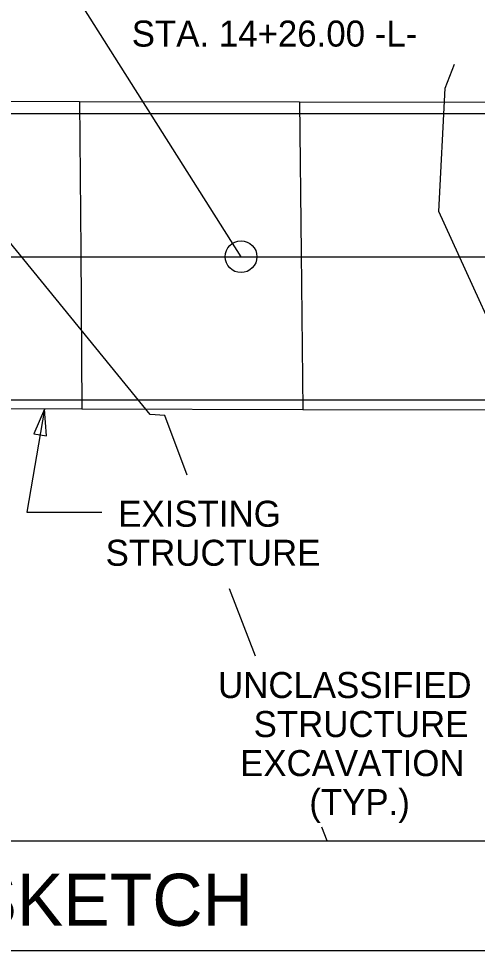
# Model space of a CAD drawing. Extents: x -20 to 509, y -659 to 21.
# Drawn here: x 118.1 to 153.4, y -423.4 to -351.8 of the extents above; entities that cross this region are included whole.
import ezdxf

# ---------------------------------------------------------------- set-up
doc = ezdxf.new("R2010")
doc.units = 0
for name, color, linetype in [('Arrowhead Terminators CELL', 7, 'Continuous'), ('Dimension Lines', 7, 'Continuous'), ('Exist Hydro Stream or Body of Water', 7, 'Continuous'), ('Exist Structure Major Deck Tunnel Box Culvert', 7, 'Continuous'), ('Plan Sheet CELL', 7, 'Continuous'), ('Prop EOT', 7, 'Continuous'), ('Prop Horizontal Alignment', 7, 'Continuous'), ('Text', 7, 'Continuous'), ('Title Text', 7, 'Continuous')]:
    doc.layers.add(name, color=color, linetype=linetype)

msp = doc.modelspace()

# ---------------------------------------------------------------- linework, layer by layer
at = {"layer": 'Arrowhead Terminators CELL'}
msp.add_lwpolyline([(120.138, -381.774), (119.305, -383.66), (120.291, -383.829)], close=True, dxfattribs=at)
at = {"layer": 'Dimension Lines'}
for p, q in [((135.229, -370.052), (123.143, -350.946)), ((120.138, -381.774), (118.773, -389.693)), ((118.773, -389.693), (124.545, -389.693))]:
    msp.add_line(p, q, dxfattribs=at)
msp.add_circle((135.229, -370.052), 1.22, dxfattribs=at)
at = {"layer": 'Exist Hydro Stream or Body of Water'}
for points in [[(131.08, -386.838), (129.369, -382.245), (128.25, -382.169), (117.417, -368.872), (114.493, -357.356), (113.975, -353.41), (95.563, -335.727), (80.713, -320.952)], [(172.62, -414.952), (171.034, -412.028), (162.209, -394.718), (158.096, -386.345), (157.248, -386.282), (157.152, -381.329), (150.426, -366.566), (150.897, -357.105), (151.634, -355.242)], [(136.345, -400.753), (134.343, -395.584)], [(141.843, -414.952), (141.429, -413.883)]]:
    msp.add_lwpolyline(points, dxfattribs=at)
at = {"layer": 'Exist Structure Major Deck Tunnel Box Culvert'}
for points in [[(105.001, -374.19), (104.949, -369.454), (104.839, -359.537), (104.823, -358.08), (122.822, -358.116), (139.71, -358.15), (157.653, -358.186), (157.672, -359.848), (157.785, -369.851), (157.896, -379.673), (157.921, -381.85), (139.968, -381.814), (123.014, -381.779), (105.085, -381.743)], [(122.822, -358.116), (122.915, -369.591), (123.014, -381.779)], [(139.71, -358.15), (139.837, -369.769), (139.968, -381.814)]]:
    msp.add_lwpolyline(points, dxfattribs=at)
at = {"layer": 'Plan Sheet CELL'}
msp.add_line((-3.076, -414.952), (237.897, -414.952), dxfattribs=at)
msp.add_lwpolyline([(-3.076, -423.359), (237.897, -423.359), (237.897, -313.167)], dxfattribs=at)
at = {"layer": 'Prop EOT'}
for p, q in [((-3.076, -359.052), (237.897, -359.052)), ((-3.076, -381.052), (237.897, -381.052))]:
    msp.add_line(p, q, dxfattribs=at)
at = {"layer": 'Prop Horizontal Alignment'}
msp.add_line((70.294, -370.052), (237.897, -370.052), dxfattribs=at)
msp.add_line((70.294, -370.052), (237.897, -370.052), dxfattribs=at)

# ---------------------------------------------------------------- texts
at = {"layer": 'Text'}
for s, p in [('STA. 14+26.00 -L-', (126.836, -353.903)), ('EXISTING', (125.797, -390.804)), ('STRUCTURE', (124.829, -393.804)), ('UNCLASSIFIED', (133.463, -403.968)), ('STRUCTURE', (136.195, -406.968)), ('EXCAVATION', (135.155, -409.968)), ('(TYP.)', (140.47, -412.968))]:
    msp.add_text(s, height=2, dxfattribs=at).set_placement(p)
at = {"layer": 'Title Text'}
msp.add_text('LOCATION SKETCH', height=4, dxfattribs=at).set_placement((85.612, -421.472))

doc.saveas('drawing.dxf')
